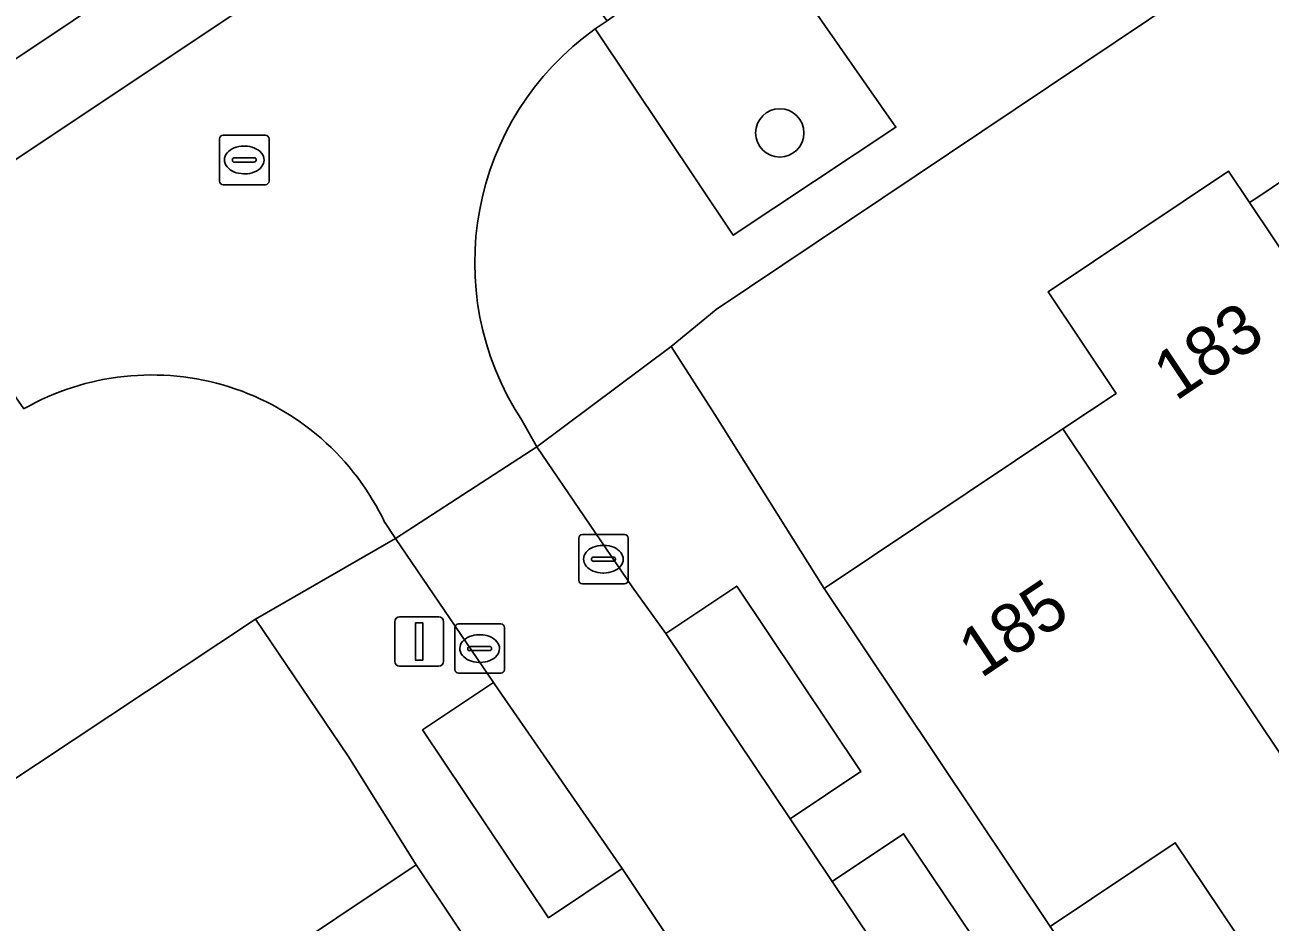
# Model space of a CAD drawing. Extents: x 158352 to 159489, y 383828 to 384603.
# Drawn here: x 158780.66 to 158805.84, y 384168.53 to 384186.67 of the extents above; entities that cross this region are included whole.
import ezdxf

# ---------------------------------------------------------------- set-up
doc = ezdxf.new("R2010")
doc.units = 0
for name, color, linetype in [('IMGEO_Boom', 7, 'Continuous'), ('IMGEO_Erf', 7, 'Continuous'), ('IMGEO_Groenvoorziening', 7, 'Continuous'), ('IMGEO_Kolk', 7, 'Continuous'), ('IMGEO_Lichtmast', 7, 'Continuous'), ('IMGEO_Pand', 7, 'Continuous'), ('IMGEO_Pand_nummerreeks', 7, 'Continuous'), ('IMGEO_Parkeervlak_open', 7, 'Continuous'), ('IMGEO_Rijbaan_lokaal_gesloten', 7, 'Continuous'), ('IMGEO_Rijbaan_lokaal_open', 7, 'Continuous'), ('IMGEO_Rioolput', 7, 'Continuous'), ('IMGEO_Voetpad_open', 7, 'Continuous')]:
    doc.layers.add(name, color=color, linetype=linetype)

msp = doc.modelspace()

# ---------------------------------------------------------------- linework, layer by layer
at = {"layer": 'IMGEO_Boom'}
msp.add_circle((158795.924, 384184.49), 0.489, dxfattribs=at)
at = {"layer": 'IMGEO_Erf'}
for points in [[(158841.042, 384212.024), (158794.638, 384180.916), (158793.73, 384180.171), (158794.611, 384178.792), (158796.822, 384175.274), (158801.648, 384178.502), (158802.724, 384179.222), (158801.35, 384181.275), (158805, 384183.716), (158805.424, 384183.083), (158805.587, 384183.192), (158806.481, 384183.79), (158810.15, 384186.245), (158814.875, 384189.406), (158819.601, 384192.568), (158824.327, 384195.729), (158829.052, 384198.891), (158833.086, 384201.589), (158833.598, 384201.932), (158833.777, 384202.052), (158833.309, 384202.752), (158836.934, 384205.178)], [(158806.369, 384166.478), (158803.921, 384170.134), (158801.394, 384168.443), (158809.26, 384156.733)]]:
    msp.add_lwpolyline(points, dxfattribs=at)
msp.add_lwpolyline([(158773.289, 384161.59), (158777.931, 384164.695), (158777.49, 384165.354), (158777.582, 384165.415), (158781.31, 384167.91), (158782.733, 384165.783), (158783.739, 384166.456), (158788.571, 384169.689), (158787.198, 384171.886), (158785.32, 384174.656), (158777.222, 384169.281), (158754.637, 384154.044), (158747.356, 384149.809), (158750.204, 384144.913), (158754.924, 384148.07), (158756.059, 384148.83), (158755.051, 384150.336), (158758.65, 384152.744), (158759.088, 384152.089), (158759.288, 384152.223), (158760.269, 384152.879), (158763.821, 384155.256), (158768.555, 384158.422)], close=True, dxfattribs=at)
at = {"layer": 'IMGEO_Groenvoorziening'}
msp.add_lwpolyline([(158792.599, 384186.878), (158792.434, 384186.755), (158792.192, 384186.594), (158794.984, 384182.421), (158798.271, 384184.606), (158796.537, 384187.087), (158796.27, 384186.921)], dxfattribs=at)
at = {"layer": 'IMGEO_Kolk'}
for p, q in [((158791.932, 384176.369), (158792.784, 384176.369)), ((158791.857, 384175.443), (158791.857, 384176.295)), ((158792.345, 384176.149), (158792.37, 384176.149)), ((158792.858, 384176.295), (158792.858, 384175.443)), ((158792.116, 384175.863), (158792.116, 384175.875)), ((158792.554, 384175.826), (158792.156, 384175.826)), ((158792.159, 384175.912), (158792.557, 384175.912)), ((158792.6, 384175.875), (158792.6, 384175.863)), ((158792.368, 384175.589), (158792.343, 384175.589)), ((158792.784, 384175.369), (158791.932, 384175.369)), ((158789.429, 384174.562), (158790.281, 384174.562)), ((158789.354, 384173.636), (158789.354, 384174.488)), ((158789.842, 384174.342), (158789.867, 384174.342)), ((158790.355, 384174.488), (158790.355, 384173.636)), ((158789.613, 384174.056), (158789.613, 384174.068)), ((158789.656, 384174.105), (158790.054, 384174.105)), ((158790.097, 384174.068), (158790.097, 384174.056)), ((158790.051, 384174.019), (158789.653, 384174.019)), ((158790.281, 384173.562), (158789.429, 384173.562)), ((158789.865, 384173.782), (158789.84, 384173.782))]:
    msp.add_line(p, q, dxfattribs=at)
for points in [[(158791.932, 384176.369), (158792.784, 384176.369)], [(158791.857, 384175.443), (158791.857, 384176.295)], [(158792.858, 384176.295), (158792.858, 384175.443)], [(158792.784, 384175.369), (158791.932, 384175.369)], [(158789.429, 384174.562), (158790.281, 384174.562)], [(158789.354, 384173.636), (158789.354, 384174.488)], [(158790.355, 384174.488), (158790.355, 384173.636)], [(158790.281, 384173.562), (158789.429, 384173.562)]]:
    msp.add_lwpolyline(points, dxfattribs=at)
for centre, radius, start, end in [((158791.934, 384176.293), 0.0765, 91.552, 178.448), ((158791.934, 384176.293), 0.0765, 91.552, 178.448), ((158792.782, 384176.293), 0.0765, 1.552, 88.448), ((158792.782, 384176.293), 0.0765, 1.552, 88.448), ((158792.156, 384175.872), 0.0403, 85.8775, 175.7526), ((158792.153, 384175.862), 0.0366, 178.938, 274.7102), ((158792.557, 384175.869), 0.043, 264.8664, 352.4533), ((158792.561, 384175.874), 0.0386, 1.7309, 96.639), ((158791.934, 384175.445), 0.0765, 181.552, 268.448), ((158791.934, 384175.445), 0.0765, 181.552, 268.448), ((158792.782, 384175.445), 0.0765, 271.552, 358.448), ((158792.782, 384175.445), 0.0765, 271.552, 358.448), ((158789.431, 384174.486), 0.0765, 91.552, 178.448), ((158789.431, 384174.486), 0.0765, 91.552, 178.448), ((158790.279, 384174.486), 0.0765, 1.552, 88.448), ((158790.279, 384174.486), 0.0765, 1.552, 88.448), ((158789.653, 384174.065), 0.0403, 85.8775, 175.7526), ((158789.65, 384174.055), 0.0366, 178.938, 274.7102), ((158790.054, 384174.062), 0.043, 264.8664, 352.4533), ((158790.058, 384174.067), 0.0386, 1.7309, 96.639), ((158789.431, 384173.638), 0.0765, 181.552, 268.448), ((158789.431, 384173.638), 0.0765, 181.552, 268.448), ((158790.279, 384173.638), 0.0765, 271.552, 358.448), ((158790.279, 384173.638), 0.0765, 271.552, 358.448)]:
    msp.add_arc(centre, radius, start, end, dxfattribs=at)
for centre, major_axis, ratio, start_param, end_param in [((158792.344, 384175.869), (-0.387, 0.002), 0.722429, 4.712389, 7.853982), ((158792.369, 384175.869), (-0.39, 0.002), 0.717154, 1.570796, 4.712389), ((158789.841, 384174.062), (-0.387, 0.002), 0.722429, 4.712389, 7.853982), ((158789.866, 384174.062), (-0.39, 0.002), 0.717154, 1.570796, 4.712389)]:
    msp.add_ellipse(centre, major_axis=major_axis, ratio=ratio, start_param=start_param, end_param=end_param, dxfattribs=at)
at = {"layer": 'IMGEO_Lichtmast'}
for p, q in [((158788.137, 384173.805), (158788.137, 384174.605)), ((158788.137, 384174.605), (158788.137, 384173.805)), ((158788.237, 384174.705), (158789.027, 384174.705)), ((158789.027, 384174.705), (158788.237, 384174.705)), ((158789.127, 384174.605), (158789.127, 384173.805)), ((158789.127, 384173.805), (158789.127, 384174.605)), ((158789.027, 384173.705), (158788.237, 384173.705)), ((158788.237, 384173.705), (158789.027, 384173.705))]:
    msp.add_line(p, q, dxfattribs=at)
msp.add_lwpolyline([(158788.557, 384174.58), (158788.707, 384174.58), (158788.707, 384173.83), (158788.557, 384173.83), (158788.557, 384174.58)], dxfattribs=at)
for centre, start, end in [((158788.237, 384174.605), 90, 180), ((158788.237, 384174.605), 90, 180), ((158789.027, 384174.605), 0, 90), ((158789.027, 384174.605), 360, 90), ((158788.237, 384173.805), 180, 270), ((158788.237, 384173.805), 180, 270), ((158789.027, 384173.805), 270, 0), ((158789.027, 384173.805), 270, 0)]:
    msp.add_arc(centre, 0.1, start, end, dxfattribs=at)
at = {"layer": 'IMGEO_Pand'}
for points in [[(158810.15, 384186.245), (158806.481, 384183.79), (158805.587, 384183.192), (158805.424, 384183.083), (158809.849, 384176.468), (158810.093, 384176.104), (158812.397, 384177.645), (158814.806, 384174.043), (158817.228, 384175.663), (158817.111, 384175.837)], [(158810.093, 384176.104), (158809.849, 384176.468), (158805.424, 384183.083), (158805, 384183.716), (158801.35, 384181.275), (158802.724, 384179.222), (158801.648, 384178.502), (158808.664, 384168.014), (158810.525, 384169.26), (158811.208, 384169.717), (158810.247, 384171.154), (158812.428, 384172.613)], [(158808.664, 384168.014), (158801.648, 384178.502), (158796.822, 384175.274), (158801.394, 384168.443), (158803.921, 384170.134), (158806.369, 384166.478)], [(158788.571, 384169.689), (158783.739, 384166.456), (158790.756, 384155.965), (158793.147, 384157.565), (158795.589, 384159.199), (158793.143, 384162.855)]]:
    msp.add_lwpolyline(points, close=True, dxfattribs=at)
at = {"layer": 'IMGEO_Parkeervlak_open'}
msp.add_lwpolyline([(158756.613, 384170.048), (158784.422, 384188.633), (158795.826, 384196.626), (158802.34, 384200.987), (158801.626, 384200.892), (158800.21, 384201.209)], dxfattribs=at)
for points in [[(158793.621, 384174.365), (158796.133, 384170.618), (158797.564, 384171.577), (158795.052, 384175.324)], [(158792.736, 384169.614), (158790.298, 384173.141), (158790.136, 384173.378), (158788.701, 384172.416), (158791.248, 384168.616)], [(158796.984, 384169.349), (158799.507, 384165.586), (158800.95, 384166.554), (158798.427, 384170.317)]]:
    msp.add_lwpolyline(points, close=True, dxfattribs=at)
at = {"layer": 'IMGEO_Rijbaan_lokaal_gesloten'}
msp.add_lwpolyline([(158801.066, 384197.693), (158804.21, 384199.782), (158803.043, 384201.515), (158802.34, 384200.987), (158795.826, 384196.626), (158784.422, 384188.633), (158756.613, 384170.048), (158757.561, 384168.674)], close=True, dxfattribs=at)
at = {"layer": 'IMGEO_Rijbaan_lokaal_open'}
for points in [[(158833.556, 384216.278), (158832.123, 384218.384), (158824.254, 384213.149), (158819.204, 384209.77), (158818.226, 384211.198), (158818.138, 384211.137), (158816.531, 384210.036), (158803.043, 384201.515), (158804.21, 384199.782), (158801.066, 384197.693), (158757.561, 384168.674), (158759.023, 384166.554), (158779.647, 384180.327), (158780.635, 384178.907)], [(158792.192, 384186.594), (158792.434, 384186.755), (158791.418, 384188.112), (158833.556, 384216.278)], [(158787.941, 384176.601), (158788.151, 384176.288), (158791.011, 384178.139), (158790.706, 384178.683)]]:
    msp.add_lwpolyline(points, dxfattribs=at)
msp.add_lwpolyline([(158799.507, 384165.586), (158796.984, 384169.349), (158796.133, 384170.618), (158793.621, 384174.365), (158792.942, 384175.309), (158791.011, 384178.139), (158788.151, 384176.288), (158790.136, 384173.378), (158790.298, 384173.141), (158792.736, 384169.614), (158793.574, 384168.357), (158796.09, 384164.582), (158796.913, 384163.347), (158799.44, 384159.557), (158804.117, 384152.527), (158804.96, 384151.274), (158807.801, 384153.215), (158807.56, 384153.641), (158802.865, 384160.576), (158800.35, 384164.328)], close=True, dxfattribs=at)
for centre, radius, start, end in [((158795.563, 384181.866), 5.807, 125.488, 213.2351), ((158783.223, 384174.381), 5.214, 25.2002, 119.7651)]:
    msp.add_arc(centre, radius, start, end, dxfattribs=at)
at = {"layer": 'IMGEO_Rioolput'}
for p, q in [((158784.67, 384184.443), (158785.522, 384184.443)), ((158784.595, 384183.517), (158784.595, 384184.369)), ((158785.083, 384184.223), (158785.108, 384184.223)), ((158785.596, 384184.369), (158785.596, 384183.517)), ((158784.854, 384183.937), (158784.854, 384183.949)), ((158785.292, 384183.9), (158784.894, 384183.9)), ((158784.897, 384183.986), (158785.295, 384183.986)), ((158785.338, 384183.949), (158785.338, 384183.937)), ((158785.106, 384183.663), (158785.081, 384183.663)), ((158785.522, 384183.443), (158784.67, 384183.443))]:
    msp.add_line(p, q, dxfattribs=at)
for points in [[(158784.67, 384184.443), (158785.522, 384184.443)], [(158784.595, 384183.517), (158784.595, 384184.369)], [(158785.596, 384184.369), (158785.596, 384183.517)], [(158785.522, 384183.443), (158784.67, 384183.443)]]:
    msp.add_lwpolyline(points, dxfattribs=at)
for centre, radius, start, end in [((158784.672, 384184.367), 0.0765, 91.552, 178.448), ((158784.672, 384184.367), 0.0765, 91.552, 178.448), ((158785.52, 384184.367), 0.0765, 1.552, 88.448), ((158785.52, 384184.367), 0.0765, 1.552, 88.448), ((158784.894, 384183.946), 0.0403, 85.8775, 175.7526), ((158784.891, 384183.936), 0.0366, 178.938, 274.7102), ((158785.295, 384183.943), 0.043, 264.8664, 352.4533), ((158785.299, 384183.948), 0.0386, 1.7309, 96.639), ((158784.672, 384183.519), 0.0765, 181.552, 268.448), ((158784.672, 384183.519), 0.0765, 181.552, 268.448), ((158785.52, 384183.519), 0.0765, 271.552, 358.448), ((158785.52, 384183.519), 0.0765, 271.552, 358.448)]:
    msp.add_arc(centre, radius, start, end, dxfattribs=at)
for centre, major_axis, ratio, start_param, end_param in [((158785.082, 384183.943), (-0.387, 0.002), 0.722429, 4.712389, 7.853982), ((158785.107, 384183.943), (-0.39, 0.002), 0.717154, 1.570796, 4.712389)]:
    msp.add_ellipse(centre, major_axis=major_axis, ratio=ratio, start_param=start_param, end_param=end_param, dxfattribs=at)
at = {"layer": 'IMGEO_Voetpad_open'}
for points in [[(158790.706, 384178.683), (158791.011, 384178.139), (158793.73, 384180.171), (158794.638, 384180.916), (158841.042, 384212.024)], [(158832.309, 384211.014), (158828.308, 384208.343), (158829.986, 384205.806), (158826.458, 384203.452), (158824.827, 384206.003), (158812.306, 384197.607), (158813.977, 384195.122), (158810.997, 384193.117), (158809.298, 384195.612), (158796.537, 384187.087), (158798.271, 384184.606), (158794.984, 384182.421), (158792.192, 384186.594)], [(158809.26, 384156.733), (158801.394, 384168.443), (158796.822, 384175.274), (158794.611, 384178.792), (158793.73, 384180.171), (158791.011, 384178.139), (158792.942, 384175.309), (158793.621, 384174.365), (158795.052, 384175.324), (158797.564, 384171.577), (158796.133, 384170.618), (158796.984, 384169.349), (158798.427, 384170.317), (158800.95, 384166.554), (158799.507, 384165.586), (158800.35, 384164.328), (158801.78, 384165.286), (158804.295, 384161.535), (158802.865, 384160.576), (158807.56, 384153.641)], [(158746.068, 384149.06), (158747.356, 384149.809), (158754.637, 384154.044), (158777.222, 384169.281), (158785.32, 384174.656), (158788.151, 384176.288), (158787.941, 384176.601)], [(158793.574, 384168.357), (158792.736, 384169.614), (158791.248, 384168.616), (158788.701, 384172.416), (158790.136, 384173.378), (158788.151, 384176.288), (158785.32, 384174.656), (158787.198, 384171.886), (158788.571, 384169.689), (158793.143, 384162.855)]]:
    msp.add_lwpolyline(points, dxfattribs=at)
for centre, radius, start, end in [((158795.563, 384181.866), 5.807, 125.488, 213.2351), ((158783.223, 384174.381), 5.214, 25.2002, 119.7651)]:
    msp.add_arc(centre, radius, start, end, dxfattribs=at)

# ---------------------------------------------------------------- texts
at = {"layer": 'IMGEO_Pand_nummerreeks'}
for s, rotation, p in [('183', 33.7529, (158803.928, 384179.053)), ('185', 33.764, (158799.988, 384173.446))]:
    msp.add_text(s, height=1, rotation=rotation, dxfattribs=at).set_placement(p)

doc.saveas('drawing.dxf')
